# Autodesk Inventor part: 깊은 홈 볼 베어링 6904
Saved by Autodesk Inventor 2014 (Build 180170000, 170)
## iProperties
Created: 2025-09
Part Number: 깊은 홈 볼 베어링 6904
Material: 일반
Document SubType Name: Modeling
Designer: dg
Density: 1 g/cm^3
Appearance: 기본값
Author: dg
Author: jhkim
Description: 깊은 그루브 볼 베어링
Creation Date: 2025-09-02
Sending System: Autodesk Inventor 2026
Preprocessor: ST-DEVELOPER v20.1
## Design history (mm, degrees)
node "깊은 홈 볼 베어링 69041"
body "Solid1"
node "Solid1_1"
node "Solid1_2"
node "Solid1_3"
node "Solid1_4"
node "Solid1_5"
node "Solid1_6"
node "Solid1_7"
node "Solid1_8"
node "Solid1_9"
node "Solid1_10"
node "Solid1_11"
node "기준1"
node "기준2"
node "기준3"
node "기준4"
node "기준5"
node "기준6"
node "기준7"
node "기준8"
node "기준9"
node "기준10"
node "기준11"
node "기준12"
